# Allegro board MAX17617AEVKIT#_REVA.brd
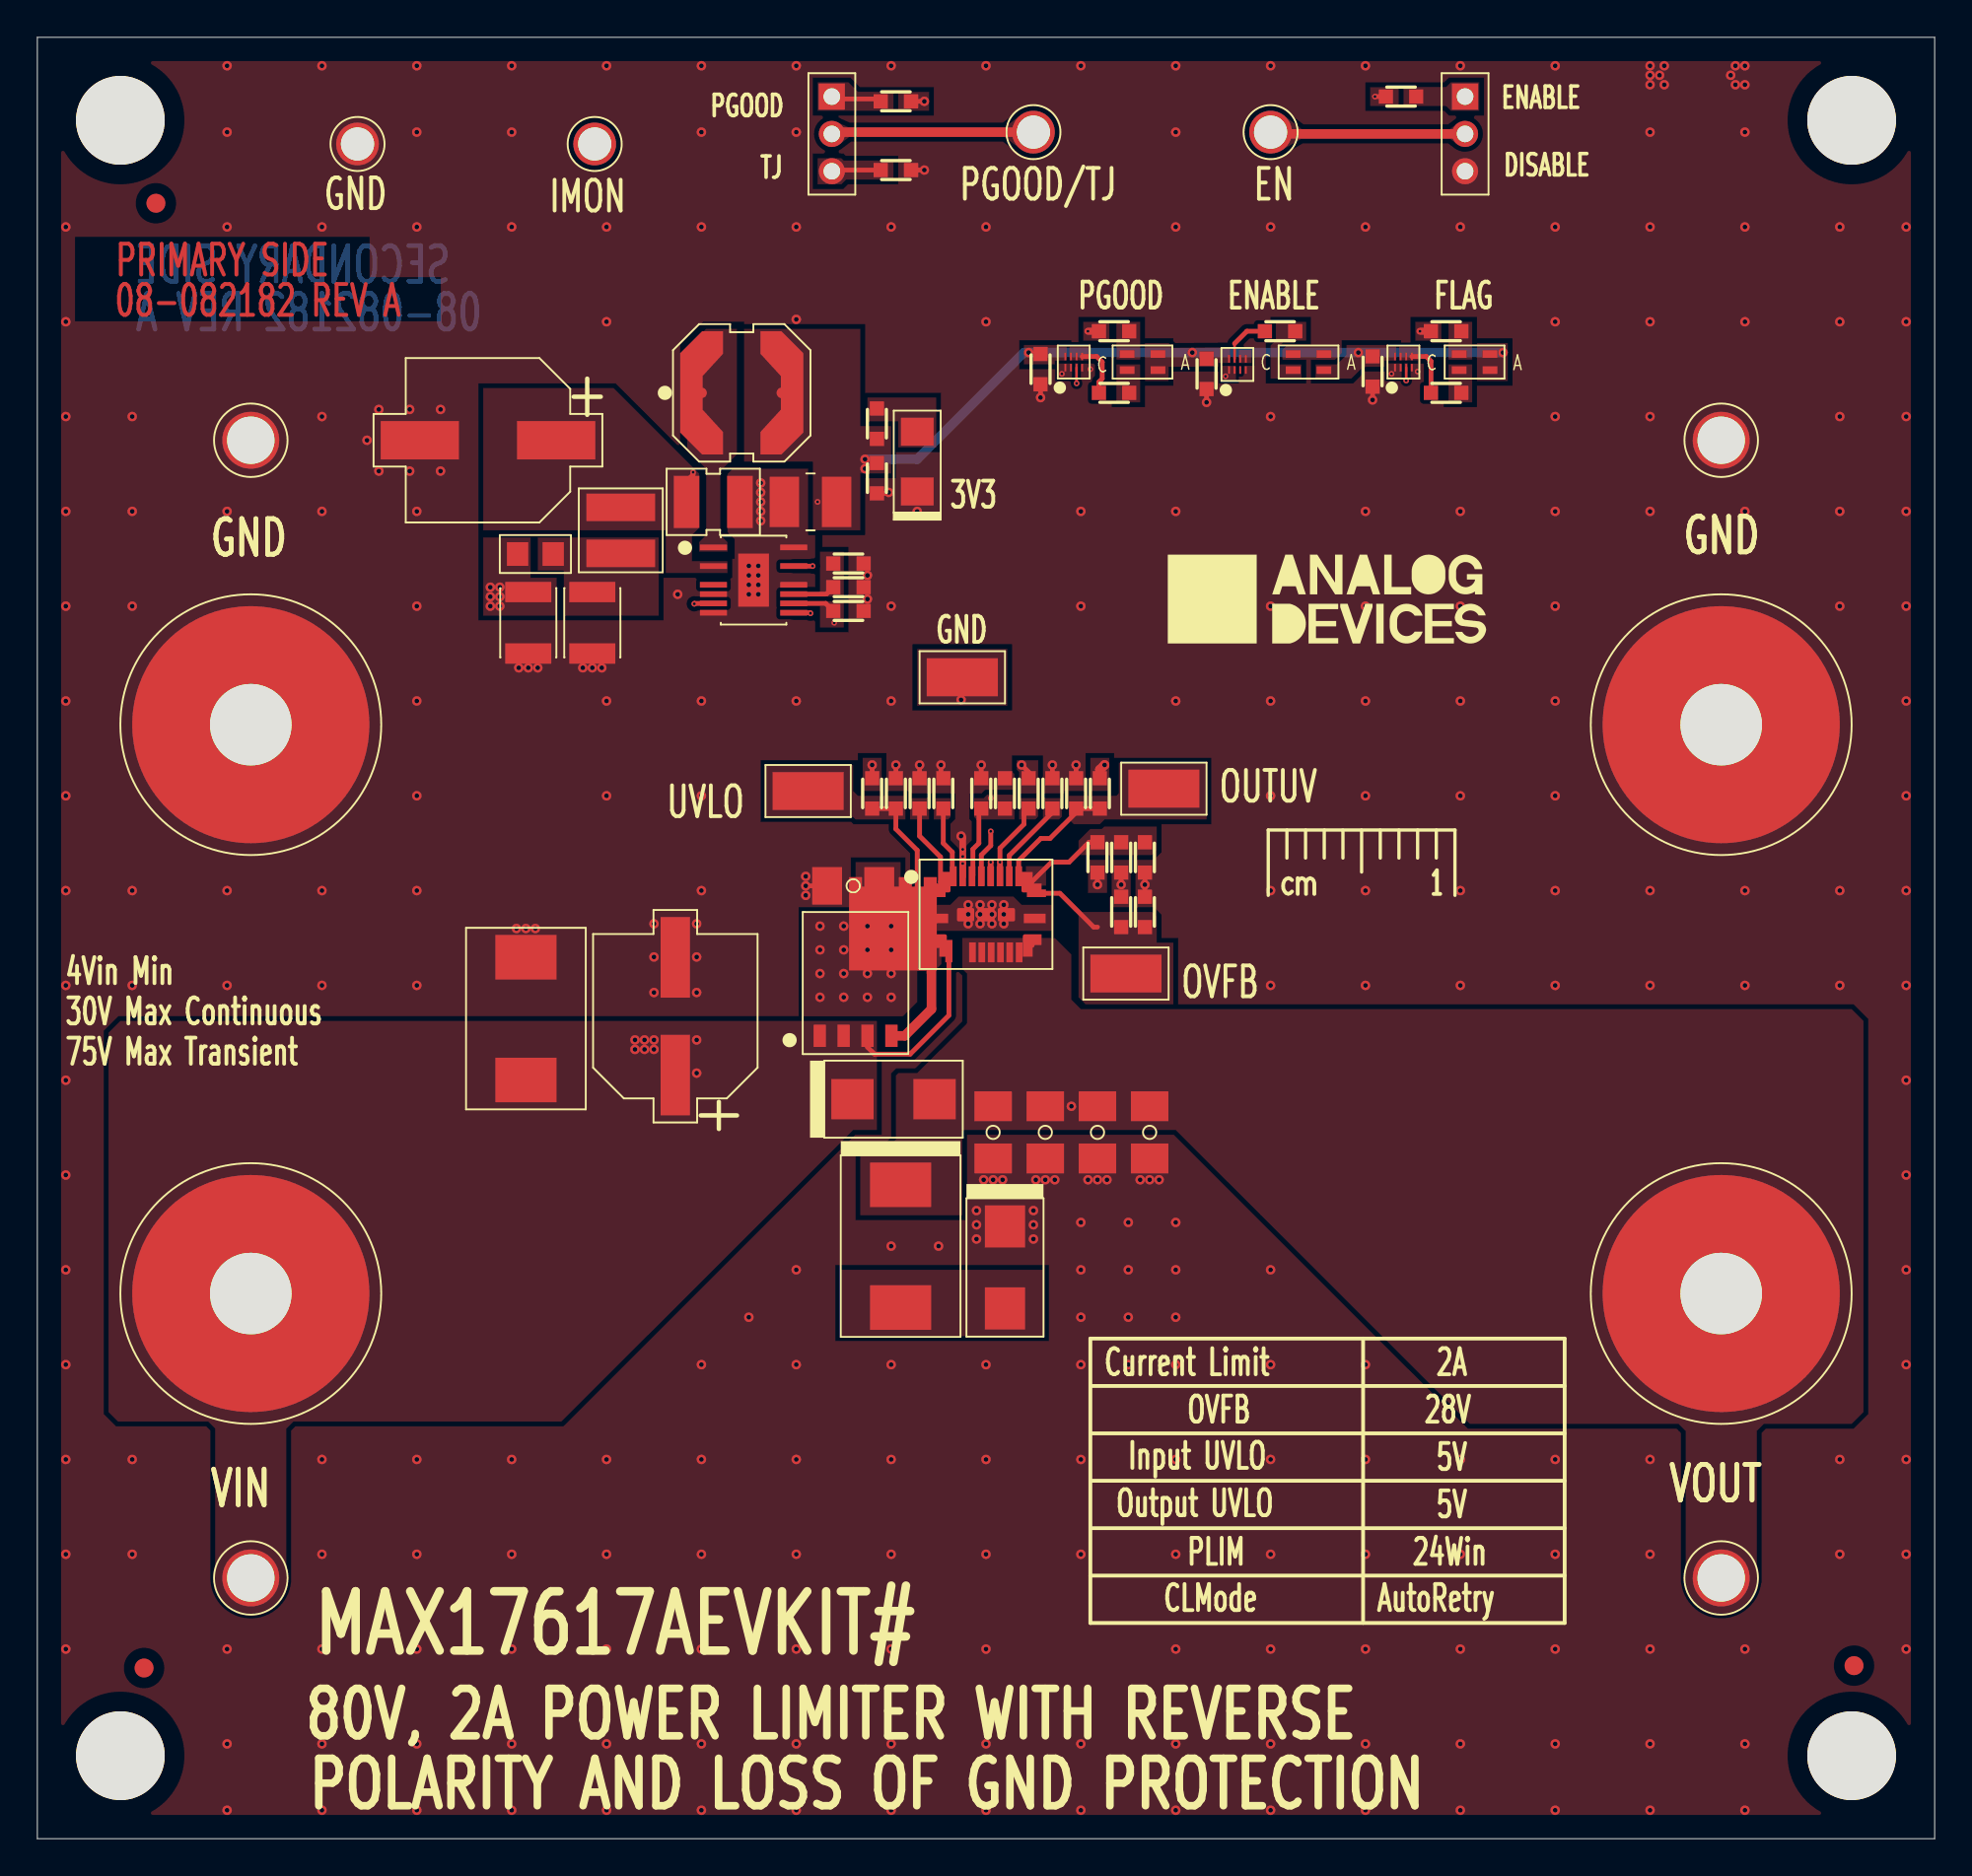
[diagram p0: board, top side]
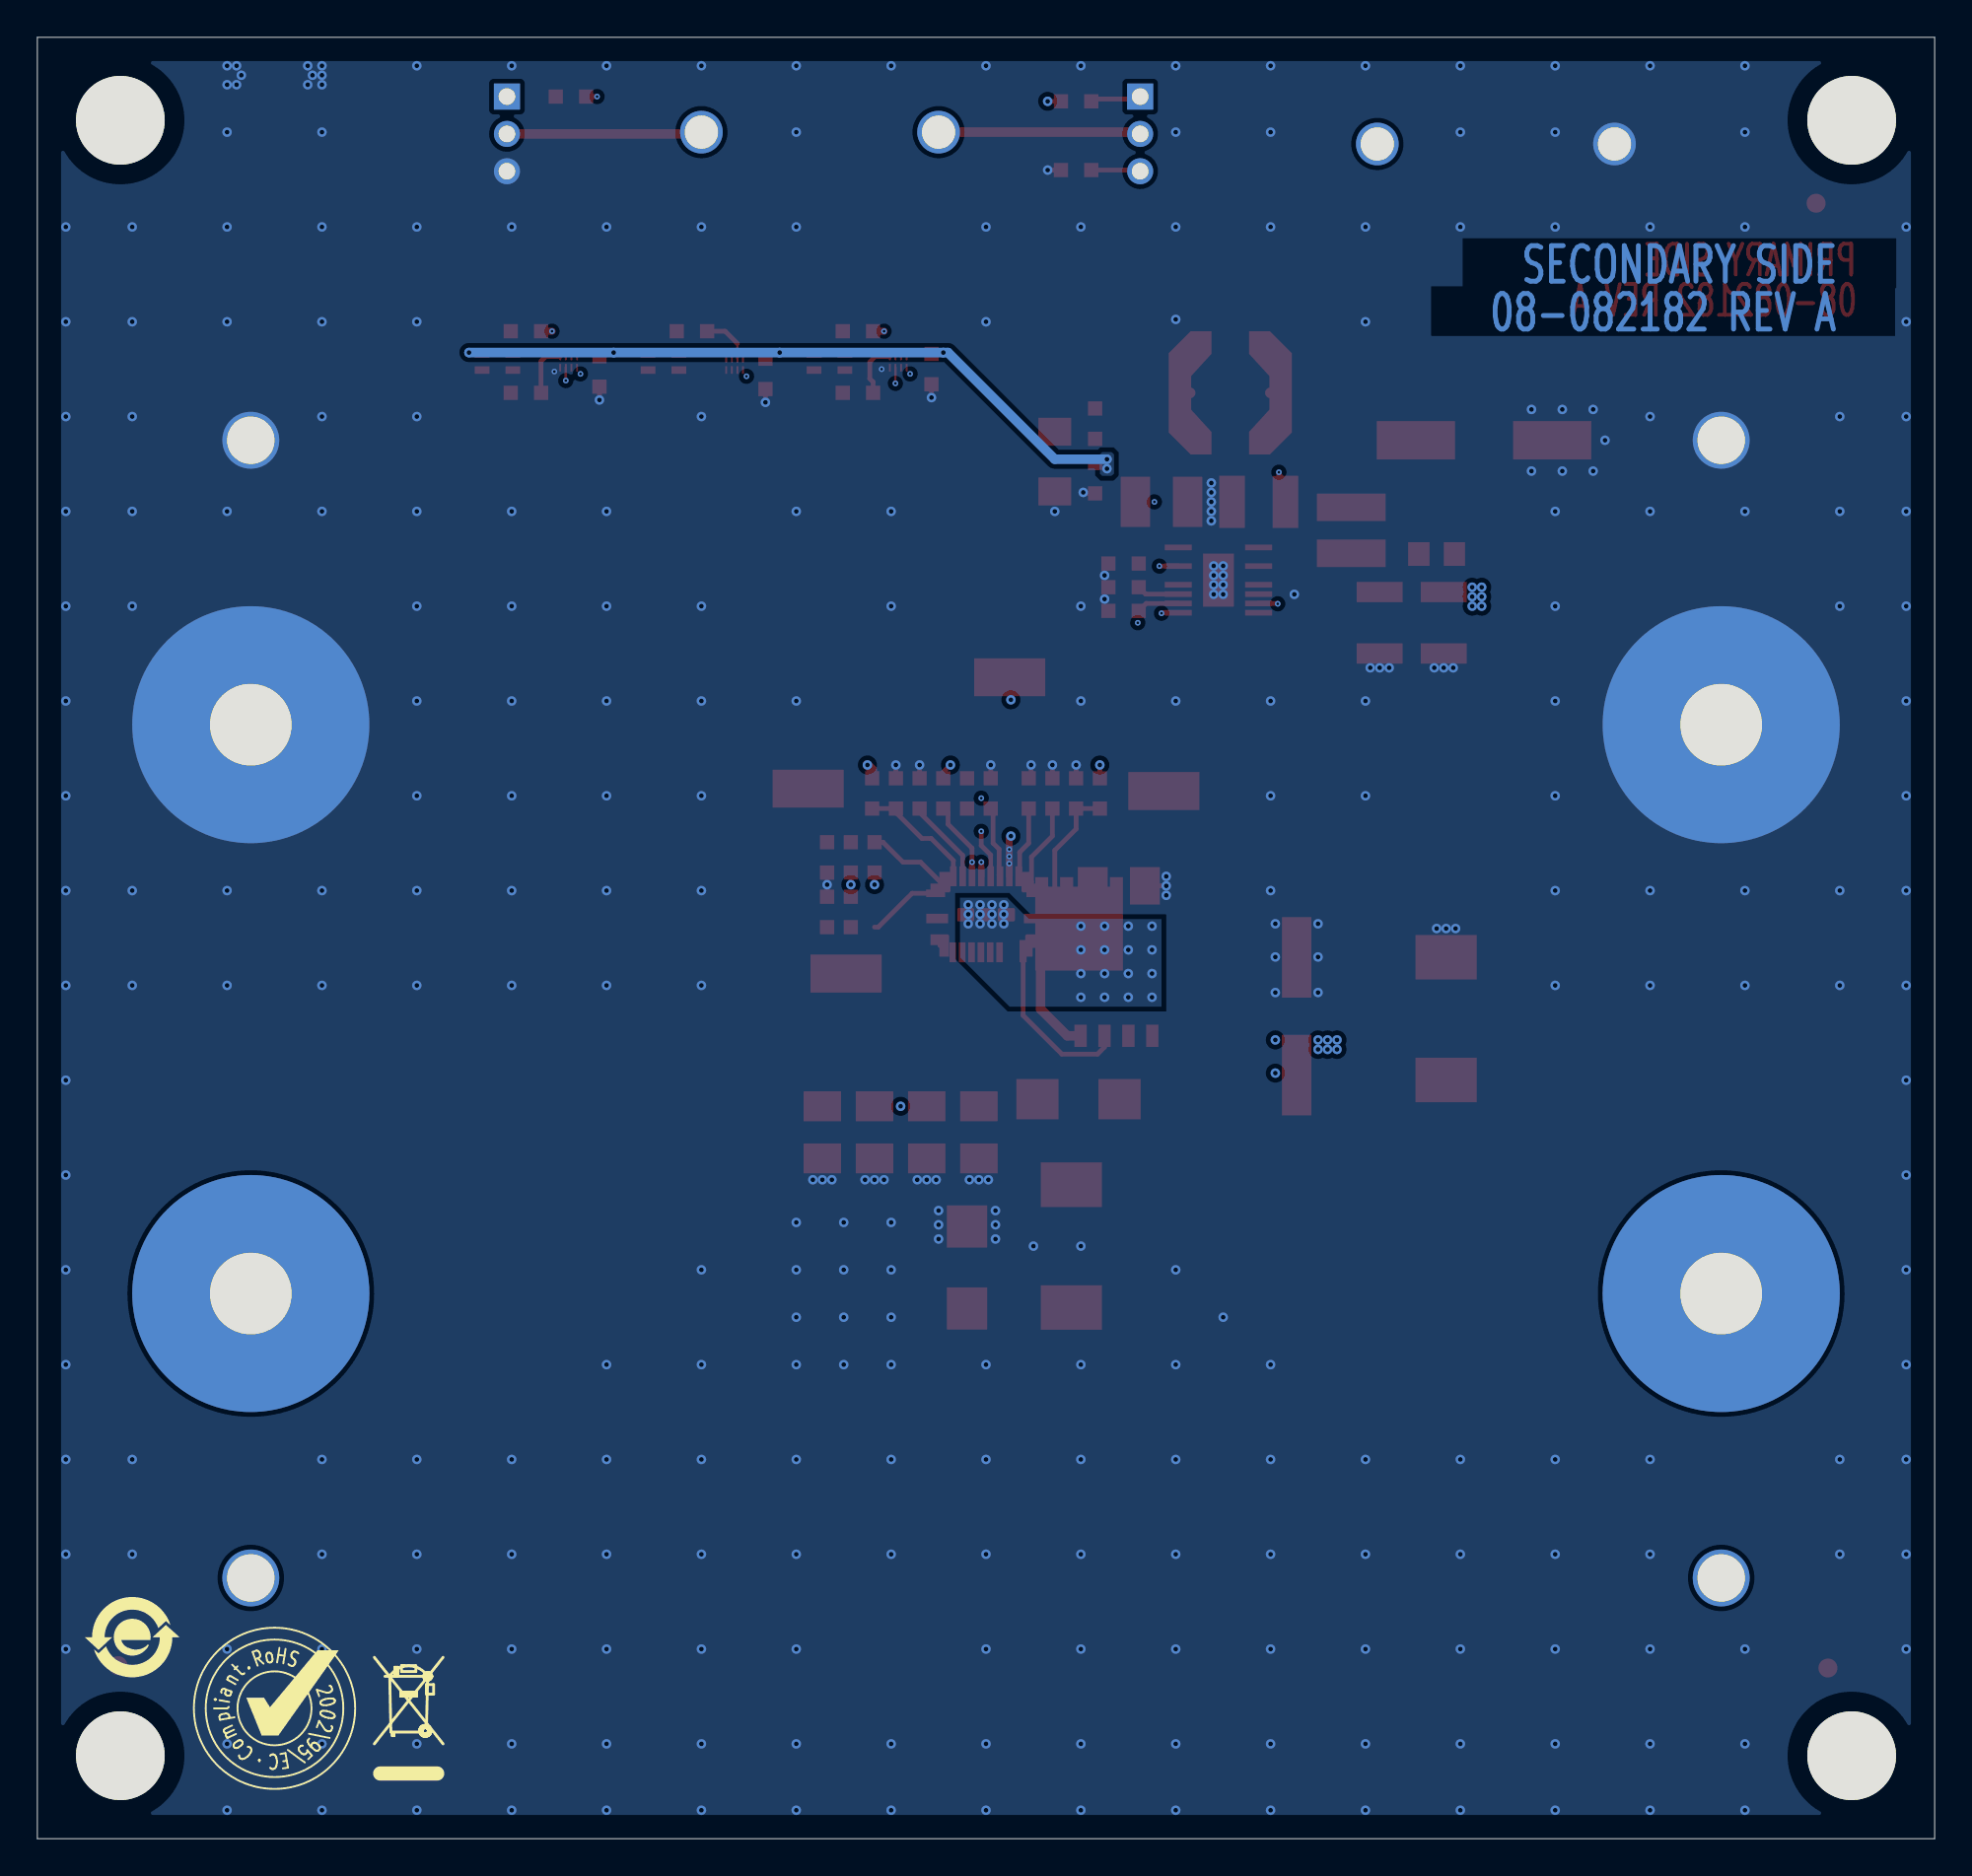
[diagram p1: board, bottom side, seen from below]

Outline 101.6 x 96.52 mm; copper layers: TOP, LAYER_2, LAYER_3, BOTTOM. Coordinates in mm from the lower left corner of the outline.
Outline path: 0,96.52 0,0 101.6,0 101.6,96.52 0,96.52

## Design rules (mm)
constraint set DEFAULT: min track width 0.254

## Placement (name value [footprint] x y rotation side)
C1  2.2uF  [C1210H87]  26.29 65.15 270 top
C2  2.2uF  [C1210H87]  29.72 65.15 270 top
C3  6.8UF  [CPLSMSQ327H413]  24.13 74.93 180 top
C5  10NF  [C0603]  43.43 65.79 0 top
C6  1UF  [C1210H110]  36.2 71.63 0 top
C7  220pF  [C0603]  43.43 67.06 0 top
C8  22uF  [C1210-2]  41.4 71.63 180 top
C11  0.1uF  [C0603]  44.96 72.9 270 top
C12  4.7UF  [CPLSMSQ327H256]  34.16 44.07 90 top
C13  0.1uF  [C0603]  71.5 78.61 270 top
C14  1uF  [C1206H71]  43.69 51.05 180 top
C15  2.2uF  [C0603]  48.51 56.01 90 top
C16  0.1uF  [C0603]  53.72 78.74 270 top
C17  4.7uF  [C1206H71]  51.18 37.85 270 top
C18  4.7uF  [C1206H71]  53.98 37.85 270 top
C19  4.7uF  [C1206H71]  56.77 37.85 270 top
C20  4.7uF  [C1206H71]  59.56 37.85 270 top
C21  0.1uF  [C0603]  62.61 78.49 270 top
C22  TBD0603  [C0603]  50.55 56.01 90 top
D1  APTB1612ESGC-F01  [LEDSML63W49H33]  76.96 79.12 180 top
D2  APTB1612ESGC-F01  [LEDSML63W49H33]  59.18 79.12 180 top
D3  APTB1612ESGC-F01  [LEDSML63W49H33]  68.07 79.12 180 top
D4  SMCJ48CA  [DO214AB_A]  26.16 43.94 90 top
D5  1KSMB62A  [DO214AA_A]  45.85 39.62 0 top
D6  SMCJ48A  [DO214AB-4]  46.23 31.75 270 top
D7  SMBJ51A  [DO214AA_A]  51.82 30.61 270 top
DS1  SML-LX1206GW-TR  [LEDSML126W63H43]  47.12 73.79 90 top
E1  330OHM  [L0805H50]  26.67 68.83 0 top
JP1  62000311121  [CNTHMHDR1X3L236W79H244]  76.45 93.34 270 top
JP2  62000311121  [CNTHMHDR1X3L236W79H244]  42.55 93.34 270 top
L1  2.2UH  [LSMSQ157H83]  31.24 70.1 90 top
L2  150UH  [LSMSQ236H138]  37.72 77.47 0 top
NOREF  -  []  -76.2 -81.28 0 top
NOREF#2  -  [unnamed#2]  97.28 9.27 0 top
NOREF#3  -  []  0 96.52 270 top
NOREF#4  -  []  289.56 206.95 0 top
NOREF#5  -  []  249.05 247.01 0 top
NOREF#6  -  []  0 96.52 0 top
NOREF#7  -  [unnamed#2]  5.71 9.14 0 top
NOREF#8  -  []  -76.2 -81.28 0 top
NOREF#9  -  []  65.91 50.55 0 top
NOREF#10  -  []  -76.2 -81.28 0 top
NOREF#11  -  []  -222.25 -151.13 0 top
NOREF#12  -  [unnamed#2]  97.16 4.45 180 top
NOREF#13  -  [unnamed#2]  4.45 4.45 180 top
NOREF#14  -  [unnamed#2]  4.45 92.08 180 top
NOREF#15  -  []  101.6 0 90 top
NOREF#16  -  []  310.64 65.34 0 top
NOREF#17  -  []  101.6 96.52 180 top
NOREF#18  -  []  53.59 102.49 0 top
NOREF#19  -  []  13.84 84.2 270 top
NOREF#20  -  []  101.6 0 90 top
NOREF#21  -  []  12.18 2.18 0 top
NOREF#22  -  []  244.98 275.02 0 top
NOREF#23  -  []  0 0 0 top
NOREF#24  -  [unnamed#2]  97.16 92.08 180 top
NOREF#25  -  []  7.24 56.26 0 top
NOREF#26  -  []  69.09 66.42 0 top
NOREF#27  -  [unnamed#2]  6.35 87.63 0 top
NOREF#28  -  []  338.84 108.52 0 top
NOREF#29  -  []  -222.25 -151.13 0 top
NOREF#30  -  []  9.78 298.32 0 top
NOREF#31  -  []  10.95 33.4 0 top
NOREF#32  -  []  81.92 3.17 180 bottom
NOREF#33  -  []  88.9 6.99 180 bottom
NOREF#34  -  []  96.52 10.79 180 bottom
Q1  SIR876ADP-T1-GE3  [SON8]  43.81 45.85 0 top
R1  7.32K  [R0603]  47.24 56.01 90 top
R2  3.83K  [R0603]  51.82 56.01 90 top
R3  220K  [R0603]  43.43 68.33 0 top
R9  1K  [R0603]  44.96 75.82 90 top
R10  1K  [R0603]  75.44 77.47 0 top
R11  1K  [R0603]  75.44 80.77 0 top
R12  442K  [R0603]  44.7 56.01 270 top
R13  100K  [R0603]  45.97 56.01 90 top
R14  64.9K  [R0603]  54.36 56.01 90 top
R15  100K  [R0603]  53.09 56.01 90 top
R16  1K  [R0603]  57.66 77.47 0 top
R17  1K  [R0603]  57.66 80.77 0 top
R18  100K  [R0603]  45.97 93.09 180 top
R19  100K  [R0603]  55.63 56.01 90 top
R20  442K  [R0603]  56.9 56.01 270 top
R22  28K  [R0603]  59.31 49.66 90 top
R23  392K  [R0603]  56.77 52.58 90 top
R24  10K  [R0603]  59.31 52.58 270 top
R25  1K  [R0603]  66.55 80.77 0 top
R26  953K  [R0603]  58.04 49.66 270 top
R27  392K  [R0603]  58.04 52.58 90 top
R28  10K  [R0603]  45.97 89.41 0 top
R29  10K  [R0603]  73.03 93.34 180 top
TP1  2501-2-00-80-00-00-07-0  [CNMILLMAX2501]  11.43 13.97 0 top
TP2  RED  [CN-BNDG-POST]  11.43 29.21 0 top
TP3  BLK  [CN-BNDG-POST]  11.43 59.69 0 top
TP4  2501-2-00-80-00-00-07-0  [CNMILLMAX2501]  11.43 74.93 0 top
TP5  2308-2-00-80-00-00-07-0  [CNMILLMAX2308]  66.04 91.44 0 top
TP6  5019  [CNKEY5019]  41.27 56.13 0 top
TP7  5019  [CNKEY5019]  49.53 62.23 0 top
TP8  5019  [CNKEY5019]  58.29 46.35 0 top
TP9  2308-2-00-80-00-00-07-0  [CNMILLMAX2308]  53.34 91.44 0 top
TP10  5019  [CNKEY5019]  60.33 56.26 0 top
TP11  2501-2-00-80-00-00-07-0  [CNMILLMAX2501]  90.17 13.97 0 top
TP12  2501-2-00-80-00-00-07-0  [CNMILLMAX2501]  90.17 74.93 0 top
TP13  RED  [CN-BNDG-POST]  90.17 29.21 0 top
TP14  BLK  [CN-BNDG-POST]  90.17 59.69 0 top
TP15  2308-2-00-80-00-00-07-0  [CNMILLMAX2308]  29.84 90.81 0 top
TP16  2308-2-00-80-00-00-07-0  [CNMILLMAX2308]  17.14 90.81 0 top
U1  MAX17617AAFD+  [QFN23_5_75X4_5_3EP]  50.8 49.53 0 top
U2  LTC3639EMSE#PBF  [MSOP16_PAD2_845X1_651_12P_05-08-1871]  38.35 67.44 270 top
U3  74LVC2G02RA3-7  [PDFN8_1_2X1]  73.15 79.12 0 top
U4  74LVC2G02RA3-7  [PDFN8_1_2X1]  55.5 79.12 0 top
U5  74LVC2G02RA3-7  [PDFN8_1_2X1]  64.26 78.99 0 top

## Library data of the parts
C1 C2 = CAP: Tolerance: 10; User Part Number: UPN; alternate symbols: (C1210H87); part number: CAP_SM-2.2UF,100V,10,E015185,C1210H87; tolerance: 10
C3 = CAPP: User Part Number: UPN; Tolerance: 20; alternate symbols: (CPLSMSQ327H413); part number: CAPP_SM-6.8UF,160V,20,E063202,CPLSMSQ327H413; tolerance: 20
C5 = CAP: Tolerance: 10; User Part Number: UPN; alternate symbols: (C0603); part number: CAP_SM-10NF,16V,10,E042810,C0603; tolerance: 10
C6 = CAP: Tolerance: 10; User Part Number: UPN; alternate symbols: (C1210H110); part number: CAP_SM-1UF,100V,10,E042933,C1210H110; tolerance: 10
C7 = CAP: Tolerance: 5; User Part Number: UPN; alternate symbols: (C0603); part number: CAP_SM-220PF,50V,5,E000417,C0603; tolerance: 5
C8 = CAP: Tolerance: 10; User Part Number: UPN; alternate symbols: (C1210-2); part number: CAP_SM-22UF,16V,10,E011548,C1210-2; tolerance: 10
C11 C13 C16 C21 = CAP: Tolerance: 10; User Part Number: UPN; alternate symbols: (C0603); part number: CAP_SM-0.1UF,16V,10,E015036,C0603; tolerance: 10
C12 = CAPP: User Part Number: UPN; Tolerance: 20; alternate symbols: (CPLSMSQ327H256); part number: CAPP_SM-4.7UF,100V,20,E046198,CPLSMSQ327H256; tolerance: 20
C14 = CAP: Tolerance: 10; User Part Number: UPN; alternate symbols: (C1206H71); part number: CAP_SM-1UF,100V,10,E031665,C1206H71; tolerance: 10
C15 = CAP: Tolerance: 10; User Part Number: UPN; alternate symbols: (C0603); part number: CAP_SM-2.2UF,10V,10,E015288,C0603; tolerance: 10
C17-C20 = CAP: Tolerance: 10; User Part Number: UPN; alternate symbols: (C1206H71); part number: CAP_SM-4.7UF,100V,10,E034771,C1206H71; tolerance: 10
C22 = CAP: User Part Number: UPN; alternate symbols: (C0603); part number: CAP_SM-TBD0603,TBD0603,TBD0603,E000382,C0603
D1-D3 = DIOLED_4P_V5: Tolerance: www.kingbright.com; User Part Number: UPN; alternate symbols: (LEDSML63W49H33); part number: DIOLED_4P_V5_SM-APTB1612ESGC-F01,2V/2.2V,N/A,E028120,LEDSML63W49H33; tolerance: www.kingbright.com
D4 = DIOTVS_BIDIR: User Part Number: UPN; Tolerance: N/A; alternate symbols: (DO214AB_A); part number: DIOTVS_BIDIR_SM-SMCJ48CA,48V,N/A,E059886,DO214AB_A; tolerance: N/A
D5 = DIOTVS: User Part Number: UPN; Tolerance: N/A; alternate symbols: (DO214AA_A); part number: DIOTVS_SM-1KSMB62A,53V,N/A,E059891,DO214AA_A; tolerance: N/A
D6 = DIOTVS: User Part Number: UPN; Tolerance: N/A; alternate symbols: (DO214AB-4); part number: DIOTVS_SM-SMCJ48A,N/A,N/A,E019000,DO214AB-4; tolerance: N/A
D7 = DIOZNR: User Part Number: UPN; Tolerance: N/A; alternate symbols: (DO214AA_A); part number: DIOZNR_SM-SMBJ51A,51V,N/A,E043431,DO214AA_A; tolerance: N/A
DS1 = DIOLED: Tolerance: N/A; User Part Number: UPN; alternate symbols: (LEDSML126W63H43); part number: DIOLED_SM-SML-LX1206GW-TR,N/A,N/A,E008009,LEDSML126W63H43; tolerance: N/A
E1 = FERRITE: Tolerance: 25; User Part Number: UPN; alternate symbols: (L0805H50); part number: FERRITE_SM-330OHM,25,E016893,L0805H50; tolerance: 25
JP1 JP2 = CN3P: User Part Number: UPN; Tolerance: N/A; alternate symbols: (CNTHMHDR1X3L236W79H244); part number: CN3P_TH-62000311121,E033291,CNTHMHDR1X3L236W79H244; tolerance: N/A
L1 = IND: User Part Number: UPN; Tolerance: 20; alternate symbols: (LSMSQ157H83); part number: IND_SM-2.2UH,20,E051506,LSMSQ157H83; tolerance: 20
L2 = IND: User Part Number: UPN; Tolerance: 20; alternate symbols: (LSMSQ236H138); part number: IND_SM-150UH,20,E046122,LSMSQ236H138; tolerance: 20
Q1 = TRANNMOSFET8P: Tolerance: N/A; User Part Number: UPN; alternate symbols: (SON8); part number: TRANNMOSFET8P_SM-SIR876ADP-T1-GE3,E059889,SON8; tolerance: N/A
R1 = RES: Tolerance: 1; User Part Number: UPN; alternate symbols: (R0603); part number: RES_SM-7.32K,E024630,1/10W,1,R0603; tolerance: 1
R2 = RES: Tolerance: 1; User Part Number: UPN; alternate symbols: (R0603); part number: RES_SM-3.83K,E066481,1/10W,1,R0603; tolerance: 1
R3 = RES: Tolerance: 1; User Part Number: UPN; alternate symbols: (R0603); part number: RES_SM-220K,E042876,1/10W,1,R0603; tolerance: 1
R9-R11 R16 R17 R25 = RES: Tolerance: 1; User Part Number: UPN; alternate symbols: (R0603); part number: RES_SM-1K,E003678,1/10W,1,R0603; tolerance: 1
R12 R20 = RES: Tolerance: 1; User Part Number: UPN; alternate symbols: (R0603); part number: RES_SM-442K,E042881,1/10W,1,R0603; tolerance: 1
R13 R15 R18 R19 = RES: Tolerance: 1; User Part Number: UPN; alternate symbols: (R0603); part number: RES_SM-100K,E010279,1/10W,1,R0603; tolerance: 1
R14 = RES: Tolerance: 1; User Part Number: UPN; alternate symbols: (R0603); part number: RES_SM-64.9K,E010256,1/10W,1,R0603; tolerance: 1
R22 = RES: Tolerance: 1; User Part Number: UPN; alternate symbols: (R0603); part number: RES_SM-28K,E019092,1/10W,1,R0603; tolerance: 1
R23 R27 = RES: Tolerance: 1; User Part Number: UPN; alternate symbols: (R0603); part number: RES_SM-392K,E060084,1/10W,1,R0603; tolerance: 1
R24 R28 R29 = RES: Tolerance: 1; User Part Number: UPN; alternate symbols: (R0603); part number: RES_SM-10K,E003671,1/10W,1,R0603; tolerance: 1
R26 = RES: Tolerance: 1; User Part Number: UPN; alternate symbols: (R0603); part number: RES_SM-953K,E067819,1/10W,1,R0603; tolerance: 1
TP1 TP4 TP11 TP12 = CNTP1P: User Part Number: UPN; Tolerance: N/A; alternate symbols: (CNMILLMAX2501); part number: CNTP1P_TH-2501-2-00-80-00-00-07-0,E031108,CNMILLMAX2501; tolerance: N/A
TP2 TP13 = CNTP1P: Tolerance: N/A; User Part Number: UPN; alternate symbols: (CN-BNDG-POST); part number: CNTP1P_TH-RED,E005767,CN-BNDG-POST; tolerance: N/A
TP3 TP14 = CNTP1P: Tolerance: N/A; User Part Number: UPN; alternate symbols: (CN-BNDG-POST); part number: CNTP1P_TH-BLK,E005768,CN-BNDG-POST; tolerance: N/A
TP5 TP9 TP15 TP16 = CNTP1P: User Part Number: UPN; Tolerance: N/A; alternate symbols: (CNMILLMAX2308); part number: CNTP1P_TH-2308-2-00-80-00-00-07-0,E030692,CNMILLMAX2308; tolerance: N/A
TP6-TP8 TP10 = CNTP1P: User Part Number: UPN; Tolerance: N/A; alternate symbols: (CNKEY5019); part number: CNTP1P_SM-5019,E021431,CNKEY5019; tolerance: N/A
U1 = ADMAX17617A: User Part Number: UPN; Tolerance: N/A; alternate symbols: (QFN23_5_75X4_5_3EP); part number: ADMAX17617A_SM-MAX17617AAFD+,E059964,QFN23_5_75X4_5_3EP; tolerance: N/A
U2 = ADLTC3639: Tolerance: N/A; User Part Number: UPN; alternate symbols: (MSOP16_PAD2_845X1_651_12P_05-08-1871); part number: ADLTC3639_SM-LTC3639EMSE#PBF,E048616,MSOP16_PAD2_845X1_651_12P_05-08-1871; tolerance: N/A
U3-U5 = 7402_V2: User Part Number: UPN; Tolerance: N/A; alternate symbols: (PDFN8_1_2X1); part number: 7402_V2_SM-74LVC2G02RA3-7,E026705,PDFN8_1_2X1; tolerance: N/A

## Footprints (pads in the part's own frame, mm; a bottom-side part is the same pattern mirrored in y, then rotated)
C0603
  rect 0.762x0.762 smd: 1(-0.813,0) 2(0.813,0)
C1206H71
  rect 1.6x2.007 smd: 1(-1.397,0) 2(1.397,0)
C1210-2
  rect 1.575x2.692 smd: 1(-1.397,0) 2(1.397,0)
C1210H87
  rect 1.092x2.464 smd: 1(-1.646,0) 2(1.646,0)
C1210H110
  rect 1.372x2.794 smd: 1(-1.431,0) 2(1.431,0)
CN-BNDG-POST
  round 12.7 hole 4.369: 1(0,0)
CNKEY5019
  rect 3.81x2.032 smd: 1(0,0)
CNMILLMAX2308
  round 2.286 hole 1.778: 1(0,0)
CNMILLMAX2501
  round 3.048 hole 2.54: 1(0,0)
CNTHMHDR1X3L236W79H244
  rect 1.397x1.397 hole 0.889: 1(0,0)
  round 1.397 hole 0.889: 2(2,0) 3(4,0)
CPLSMSQ327H256
  rect 4.318x1.575 smd: N(3.154,0) P(-3.154,0)
CPLSMSQ327H413
  rect 4.191x2.057 smd: N(3.65,0) P(-3.65,0)
DO214AA_A
  rect 2.261x2.159 smd: A(2.197,0) C(-2.197,0)
DO214AB-4
  rect 2.388x3.277 smd: A(3.289,0) C(-3.289,0)
DO214AB_A
  rect 2.388x3.277 smd: 1(-3.289,0) 2(3.289,0)
L0805H50
  rect 1.143x1.27 smd: 1(-0.953,0) 2(0.953,0)
LEDSML63W49H33
  rect 0.787x0.406 smd: 1(-0.825,-0.43) 2(0.825,-0.43) 3(-0.825,0.43) 4(0.825,0.43)
LEDSML126W63H43
  rect 1.499x1.753 smd: A(1.6,0) C(-1.6,0)
LSMSQ157H83
  rect 1.473x3.683 smd: 1(-1.232,0) 2(1.232,0)
LSMSQ236H138
  custom 0.575x0.575 smd: 1(-2.151,0) 2(2.151,0)
MSOP16_PAD2_845X1_651_12P_05-08-1871
  rect 0.305x1.448 smd: 1(-1.75,-2.15) 3(-0.75,-2.15) 5(0.25,-2.15) 6(0.75,-2.15) 7(1.25,-2.15) 8(1.75,-2.15) 9(1.75,2.15) 10(1.25,2.15) 11(0.75,2.15) 12(0.25,2.15) 14(-0.75,2.15) 16(-1.75,2.15)
  rect 2.845x1.651 smd: 17(0,0)
PDFN8_1_2X1
  rect 0.102x0.406 smd: 1(-0.45,-0.3) 2(-0.15,-0.3) 3(0.15,-0.3) 4(0.45,-0.3) 5(0.45,0.3) 6(0.15,0.3) 7(-0.15,0.3) 8(-0.45,0.3)
QFN23_5_75X4_5_3EP
  custom 0.268x0.268 smd: 1(-2.436,1.723) 15(2.436,1.723)
  rect 1.016x0.406 smd: 2(-2.676,1.125) 14(2.7,1.125)
  rect 1.168x0.508 smd: 3(-2.612,-0.225) 13(2.612,-0.225)
  custom 0.218x0.218 smd: 4(-2.536,-1.674)
  rect 0.381x1.194 smd: 5(-1.988,-1.975)
  rect 0.356x1.067 smd: 6(-0.725,-2.038) 7(-0.225,-2.038) 8(0.275,-2.038) 9(0.775,-2.038) 10(1.275,-2.038) 11(1.775,-2.038) 16(1.75,2.038) 17(1.25,2.038) 18(0.75,2.038) 19(0.25,2.038) 20(-0.25,2.038) 21(-0.75,2.038) 22(-1.25,2.038) 23(-1.75,2.038)
  custom 0.249x0.249 smd: 12(2.473,-1.674)
  custom 0.179x0.179 smd: 24(-1.092,-0.023) 25(0,-0.023) 26(1.092,-0.023)
R0603
  rect 0.762x0.762 smd: 1(-0.813,0) 2(0.813,0)
SON8
  rect 0.66x1.194 smd: 1(-1.92,-2.828) 2(-0.64,-2.828) 3(0.64,-2.828) 4(1.92,-2.828)
  custom 1.175x1.175 smd: 5(2,3.171)
  round 0.127 smd: 6(0.678,3.211) 7(-0.68,3.236) 8(-2.002,3.223)
unnamed#2
  round 1.016 smd: (0,0)

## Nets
3V3: C8.1 C11.1 C13.1 C16.1 C21.1 D1.1 D1.3 D2.1 D2.3 D3.3 L2.2(N2) R9.1 R15.2(N2) R18.1 R29.2(N2) U2.9 U3.8(VCC) U4.8(VCC) U5.8(VCC)
VIN: C1.1 C12.P D4.1 D5.C E1.1 Q1.1 Q1.2 Q1.3(S3) R12.1 R23.1 TP1.1(N1) TP2.1(N1) U1.5
EN: JP1.2 TP5.1(N1) U1.19 U5.1 U5.2
FLAG: R15.1 U1.18 U3.1 U3.2
GROUND: C1.2(N2) C2.2(N2) C3.N(N2) C5.2(N2) C6.2(N2) C7.2(N2) C8.2(N2) C11.2(N2) C12.N(N2) C13.2(N2) C14.2(N2) C15.2(N2) C16.2(N2) C17.2(N2) C18.2(N2) C19.2(N2) C20.2(N2) C21.2(N2) C22.2(N2) D3.1 D3.2 D4.2(N2) D7.C DS1.C JP1.3(N3) R1.2(N2) R2.2(N2) R3.2(N2) R13.2(N2) R14.2(N2) R19.2(N2) R22.2(N2) R24.2(N2) R28.2(N2) TP3.1(N1) TP4.1(N1) TP7.1(N1) TP12.1(N1) TP14.1(N1) TP16.1(N1) U1.22 U2.6(VPRG2) U2.8 U2.12 U2.16 U2.17 U3.4 U4.4 U5.4
PGOOD/TJ: JP2.2 TP9.1(N1) U1.20 U4.1 U4.2
UNNAMED_1_ADLTC3639_I30_ISET: C7.1 R3.1 U2.11
UNNAMED_1_ADLTC3639_I30_RUN: C3.P C6.1 L1.2(N2) U2.3 U2.14
UNNAMED_1_ADLTC3639_I30_SS: C5.1 U2.7 U2.10
UNNAMED_1_ADLTC3639_I30_SW: L2.1 U2.1
UNNAMED_1_CAP_I4_N1: C2.1 E1.2(N2) L1.1
UNNAMED_1_DIOLED_I24_P: DS1.A(P) R9.2(N2)
UNNAMED_2_7402V2_I1_1Y: R10.1 U3.5 U3.6 U3.7
UNNAMED_2_7402V2_I1_2Y: R11.1 U3.3
UNNAMED_2_7402V2_I29_1Y: R16.1 U4.5 U4.6 U4.7
UNNAMED_2_7402V2_I29_2Y: R17.1 U4.3
UNNAMED_2_7402V2_I64_1Y: R25.1 U5.7
UNNAMED_2_7402V2_I64_2A: U5.5 U5.6
UNNAMED_2_ADMAX17617A_I102_GN: Q1.4 U1.4
UNNAMED_2_ADMAX17617A_I102_IMON: C22.1 R2.1 TP15.1(N1) U1.21
UNNAMED_2_ADMAX17617A_I102_IN1: C14.1 Q1.5 Q1.6 Q1.7 Q1.8 U1.3 U1.13 U1.24 U1.25 U1.26
UNNAMED_2_ADMAX17617A_I102_ISTART: R14.1 U1.17
UNNAMED_2_ADMAX17617A_I102_OUTUV: R19.1 R20.2(N2) TP10.1(N1) U1.16
UNNAMED_2_ADMAX17617A_I102_OVFB: R22.1 R26.2(N2) TP8.1(N1) U1.14
UNNAMED_2_ADMAX17617A_I102_PLIM: R23.2(N2) R24.1 R27.2(N2) U1.15
UNNAMED_2_ADMAX17617A_I102_SETI: R1.1 U1.1
UNNAMED_2_ADMAX17617A_I102_UVLO: R12.2(N2) R13.1 TP6.1(N1) U1.2
UNNAMED_2_ADMAX17617A_I102_VCC: C15.1 U1.23(VCC)
UNNAMED_2_CN3P_I11_N1: JP1.1 R29.1
UNNAMED_2_CN3P_I68_N1: JP2.1 R18.2(N2)
UNNAMED_2_CN3P_I68_N3: JP2.3(N3) R28.1
UNNAMED_2_DIOLED4PV5_I19_C1: D1.2 R11.2(N2)
UNNAMED_2_DIOLED4PV5_I19_C2: D1.4(C2) R10.2(N2)
UNNAMED_2_DIOLED4PV5_I31_C1: D2.2 R17.2(N2)
UNNAMED_2_DIOLED4PV5_I31_C2: D2.4(C2) R16.2(N2)
UNNAMED_2_DIOLED4PV5_I74_C2: D3.4(C2) R25.2(N2)
UNNAMED_2_DIOTVS_I103_P: D6.A(P) D7.A(P)
VOUT: C17.1 C18.1 C19.1 C20.1 D5.A(P) D6.C R20.1 R26.1 R27.1 TP11.1(N1) TP13.1(N1) U1.6 U1.7 U1.8 U1.9 U1.10 U1.11 U1.12

Pads without a net: U2 5; U5 3

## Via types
v1: diameter 0.305, hole 0.152, TOP to BOTTOM, 23 vias
v2: diameter 0.508, hole 0.254, TOP to BOTTOM, 393 vias

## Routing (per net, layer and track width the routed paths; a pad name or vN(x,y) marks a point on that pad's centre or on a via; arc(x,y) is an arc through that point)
3V3: length 101.2
  TOP w0.254: v1(41.4,65.66) 41.37,65.69 U2.9 ; v2(52.7,57.53) 53.09,57.15 R15.2 ; R18.1 v2(47.5,93.09) ; R29.2 v1(71.63,93.34)
  LAYER_3 w0.254: v2(70.74,79.63) 70.74,80.84 70.36,81.22 70.36,92.08 v1(71.63,93.34) ; v1(41.78,71.63) 41.78,70.1 42.67,69.22 42.67,67.56 41.4,66.29 v1(41.4,65.66)
  LAYER_3 w0.508: v2(47.5,93.09) 47.5,90.68 44.32,87.5 v2(44.32,73.91) ; v2(44.32,73.41) 44.32,71.88 52.45,63.75 52.45,57.78 v2(52.7,57.53)
  LAYER_3 w0.635: v2(44.32,73.41) v2(44.32,73.91)
  BOTTOM w0.508: v2(44.32,73.91) 47.12,73.91 52.83,79.63 v2(53.09,79.63) v2(61.85,79.63) v2(70.74,79.63) v2(78.49,79.63)
VIN: length 57.9
  TOP w0.254: R23.1 v2(56.77,51.12) ; R12.1 v2(44.7,57.53) ; Q1.3 44.46,42.41 44.83,42.04 46.74,42.04 48.81,44.11 U1.5
  LAYER_3 w0.254: v2(35.31,41.02) 51.56,41.02 56.01,45.47 56.01,50.42 v2(56.77,51.12) ; v2(35.31,42.8) 36.2,43.69 36.2,49.02 v2(44.7,57.53)
  vias: v2(24.26,67.06) v2(24.26,66.55) v2(24.26,66.04) v2(24.77,67.06) v2(24.77,66.55) v2(24.77,66.04) v2(32,42.8) v2(32,42.29) v2(32.51,42.8) v2(32.51,42.29) v2(33.02,42.8) v2(33.02,42.29)
EN: length 56.5
  TOP w0.254: 66.13,91.35 TP5.1
  TOP w0.305: U1.19 v1(51.05,52.32)
  TOP w0.508: JP1.2 66.13,91.35
  LAYER_3 w0.254: TP5.1 63.63,89.03 v1(63.63,78.36) 63.63,76.58 54.99,67.94 54.99,56.77 51.05,52.83 v1(51.05,52.32)
FLAG: length 40
  TOP w0.254: v1(51.55,52.32) 51.55,53.07 52.83,54.36 52.83,54.94 R15.1
  TOP w0.305: U1.18 v1(51.55,52.32)
  LAYER_3 w0.254: v1(72.52,78.49) 71.75,78.49 56.26,62.99 56.26,56.26 52.32,52.32 v1(51.55,52.32)
GROUND: length 19.8
  TOP w0.254: C21.2 v2(62.61,76.96) ; R24.2 v2(59.31,51.12) R22.2 ; R13.2 v2(45.97,57.53) ; C13.2 v2(71.5,77.09) ; v2(54.36,57.53) R14.2 ; R28.2 v2(47.5,89.41) ; v2(55.63,57.53) R19.2 ; C16.2 v2(53.72,77.22) ; R1.2 v2(47.24,57.53) ; v2(45.59,72.14) 45.54,72.09 C11.2 ; C14.2 v2(41.15,51.05) ; C15.2 48.39,56.95 v2(48.39,57.53) ; v2(50.55,57.53) C22.2
  TOP w0.356: v2(49.47,53.72) 49.56,53.63 v1(49.56,53.01) v1(49.56,52.63) v1(49.56,52.25) 49.55,52.24 U1.22
  LAYER_3 w0.635: v2(49.47,53.72) v2(49.47,61.02)
  vias: v1(56.39,78.74) v1(73.91,78.61) v2(1.52,86.36) v2(1.52,81.28) v2(1.52,76.2) v2(1.52,71.12) v2(1.52,66.04) v2(1.52,60.96) v2(1.52,55.88) v2(1.52,50.8) v2(1.52,45.72) v2(1.52,40.64) v2(1.52,35.56) v2(1.52,30.48) v2(1.52,25.4) v2(1.52,20.32) v2(1.52,15.24) v2(1.52,10.16) v2(5.08,76.2) v2(5.08,71.12) v2(5.08,66.04) v2(5.08,50.8) v2(5.08,45.72) v2(5.08,20.32) v2(5.08,15.24) v2(10.16,95) v2(10.16,91.44) v2(10.16,86.36) v2(10.16,71.12) v2(10.16,50.8) v2(10.16,45.72) v2(10.16,10.16) v2(10.16,5.08) v2(10.16,1.52) v2(15.24,95) v2(15.24,86.36) v2(15.24,76.2) v2(15.24,71.12) v2(15.24,50.8) v2(15.24,45.72) v2(15.24,20.32) v2(15.24,15.24) v2(15.24,10.16) v2(15.24,5.08) v2(15.24,1.52) v2(17.65,74.93) v2(18.29,76.58) v2(18.29,73.28) v2(19.94,76.58) v2(19.94,73.28) v2(20.32,95) v2(20.32,91.44) v2(20.32,86.36) v2(20.32,71.12) v2(20.32,66.04) v2(20.32,60.96) v2(20.32,55.88) v2(20.32,50.8) v2(20.32,45.72) v2(20.32,20.32) v2(20.32,15.24) v2(20.32,10.16) v2(20.32,5.08) v2(20.32,1.52) v2(21.59,76.58) v2(21.59,73.28) v2(25.4,95) v2(25.4,91.44) v2(25.4,86.36) v2(25.4,20.32) v2(25.4,15.24) v2(25.4,10.16) v2(25.4,5.08) v2(25.4,1.52) v2(25.65,48.77) v2(25.78,62.74) v2(26.16,48.77) v2(26.29,62.74) v2(26.67,48.77) v2(26.8,62.74) v2(29.21,62.74) v2(29.72,62.74) v2(30.23,62.74) v2(30.48,95) v2(30.48,86.36) v2(30.48,81.28) v2(30.48,60.96) v2(30.48,55.88) v2(30.48,20.32) v2(30.48,15.24) v2(30.48,10.16) v2(30.48,5.08) v2(30.48,1.52) v2(33.02,49.02) v2(33.02,47.24) v2(33.02,45.34) v2(34.29,66.67) v2(35.31,49.02) v2(35.31,47.24) v2(35.31,45.34) v2(35.56,95) v2(35.56,91.44) v2(35.56,86.36) v2(35.56,60.96) v2(35.56,55.88) v2(35.56,50.8) v2(35.56,25.4) v2(35.56,20.32) v2(35.56,15.24) v2(35.56,10.16) v2(35.56,5.08) v2(35.56,1.52) v2(38.1,68.2) v2(38.1,67.69) v2(38.1,67.18) v2(38.1,66.67) v2(38.1,27.94) v2(38.61,68.2) v2(38.61,67.69) v2(38.61,67.18) v2(38.61,66.67) v2(38.73,72.64) v2(38.73,72.14) v2(38.73,71.63) v2(38.73,71.12) v2(38.73,70.61) v2(40.64,95) v2(40.64,91.44) v2(40.64,86.36) v2(40.64,81.41) v2(40.64,60.96) v2(40.64,30.48) v2(40.64,25.4) v2(40.64,20.32) v2(40.64,15.24) v2(40.64,10.16) v2(40.64,5.08) v2(40.64,1.52) v2(41.15,51.56) v2(41.15,50.55) v2(44.45,67.69) v2(44.45,66.42) v2(45.72,95) v2(45.72,86.36) v2(45.72,66.04) v2(45.72,60.96) v2(45.72,31.75) v2(45.72,25.4) v2(45.72,20.32) v2(45.72,15.24) v2(45.72,10.16) v2(45.72,5.08) v2(45.72,1.52) v2(47.12,71.12) v2(48.26,31.75) v2(50.29,33.66) v2(50.29,32.89) v2(50.29,32.13) v2(50.67,35.31) v2(50.8,95) v2(50.8,86.36) v2(50.8,81.28) v2(50.8,25.4) v2(50.8,20.32) v2(50.8,15.24) v2(50.8,10.16) v2(50.8,5.08) v2(50.8,1.52) v2(51.18,35.31) v2(51.69,35.31) v2(53.34,33.66) v2(53.34,32.89) v2(53.34,32.13) v2(53.47,35.31) v2(53.98,35.31) v2(54.48,35.31) v2(55.88,95) v2(55.88,71.12) v2(55.88,66.04) v2(55.88,33.02) v2(55.88,30.48) v2(55.88,27.94) v2(55.88,25.4) v2(55.88,20.32) v2(55.88,15.24) v2(55.88,5.08) v2(55.88,1.52) v2(56.26,35.31) v2(56.77,35.31) v2(57.28,35.31) v2(58.42,33.02) v2(58.42,30.48) v2(58.42,27.94) v2(58.42,25.4) v2(59.05,35.31) v2(59.56,35.31) v2(60.07,35.31) v2(60.96,95) v2(60.96,91.44) v2(60.96,86.36) v2(60.96,71.12) v2(60.96,60.96) v2(60.96,33.02) v2(60.96,30.48) v2(60.96,27.94) v2(60.96,25.4) v2(60.96,20.32) v2(60.96,15.24) v2(60.96,10.16) v2(60.96,5.08) v2(60.96,1.52) v2(66.04,95) v2(66.04,86.36) v2(66.04,76.2) v2(66.04,66.04) v2(66.04,60.96) v2(66.04,55.88) v2(66.04,50.8) v2(66.04,45.72) v2(66.04,30.48) v2(66.04,25.4) v2(66.04,20.32) v2(66.04,15.24) v2(66.04,10.16) v2(66.04,5.08) v2(66.04,1.52) v2(71.12,95) v2(71.12,86.36) v2(71.12,71.12) v2(71.12,66.04) v2(71.12,60.96) v2(71.12,55.88) v2(71.12,50.8) v2(71.12,45.72) v2(71.12,25.4) v2(71.12,20.32) v2(71.12,15.24) v2(71.12,10.16) v2(71.12,5.08) v2(71.12,1.52) v2(76.2,95) v2(76.2,86.36) v2(76.2,71.12) v2(76.2,66.04) v2(76.2,60.96) v2(76.2,55.88) v2(76.2,50.8) v2(76.2,45.72) v2(76.2,20.32) v2(76.2,15.24) v2(76.2,10.16) v2(76.2,5.08) v2(76.2,1.52) v2(81.28,95) v2(81.28,86.36) v2(81.28,81.28) v2(81.28,76.2) v2(81.28,71.12) v2(81.28,66.04) v2(81.28,60.96) v2(81.28,55.88) v2(81.28,50.8) v2(81.28,45.72) v2(81.28,20.32) v2(81.28,15.24) v2(81.28,10.16) v2(81.28,5.08) v2(81.28,1.52) v2(86.36,95) v2(86.36,94.49) v2(86.36,93.98) v2(86.36,91.44) v2(86.36,86.36) v2(86.36,81.28) v2(86.36,76.2) v2(86.36,71.12) v2(86.36,50.8) v2(86.36,45.72) v2(86.36,20.32) v2(86.36,15.24) v2(86.36,10.16) v2(86.36,5.08) v2(86.36,1.52) v2(86.87,94.49) v2(87.12,95) v2(87.12,93.98) v2(90.68,94.49) v2(90.93,95) v2(90.93,93.98) v2(91.44,95) v2(91.44,93.98) v2(91.44,91.44) v2(91.44,86.36) v2(91.44,81.28) v2(91.44,71.12) v2(91.44,50.8) v2(91.44,45.72) v2(91.44,10.16) v2(91.44,5.08) v2(91.44,1.52) v2(96.52,86.36) v2(96.52,81.28) v2(96.52,76.2) v2(96.52,71.12) v2(96.52,66.04) v2(96.52,50.8) v2(96.52,45.72) v2(96.52,20.32) v2(96.52,15.24) v2(100.08,86.36) v2(100.08,81.28) v2(100.08,76.2) v2(100.08,71.12) v2(100.08,66.04) v2(100.08,60.96) v2(100.08,55.88) v2(100.08,50.8) v2(100.08,45.72) v2(100.08,40.64) v2(100.08,35.56) v2(100.08,30.48) v2(100.08,25.4) v2(100.08,20.32) v2(100.08,15.24) v2(100.08,10.16)
PGOOD/TJ: length 53.1
  TOP w0.254: U1.20 50.55,52.71 51.05,53.21 v1(51.05,53.98) ; 42.64,91.44 JP2.2
  TOP w0.508: TP9.1 42.64,91.44
  LAYER_3 w0.254: v1(51.05,53.98) 51.05,54.36 53.72,57.02 53.72,75.44 54.61,76.33 54.61,78.23 v1(54.86,78.49) 54.86,89.92 TP9.1
UNNAMED_1_ADLTC3639_I30_ISET: length 2.3
  TOP w0.254: C7.1 42.25,66.69 U2.11
UNNAMED_1_ADLTC3639_I30_RUN: length 11.2
  TOP w0.254: U2.14 v1(41.52,68.19) ; v1(35.12,73.22) 35.12,73.09 34.76,72.74 C6.1
  LAYER_3 w0.254: v1(41.52,68.19) 41.52,68.21 40.01,69.72 38.61,69.72 v1(35.12,73.22)
UNNAMED_1_ADLTC3639_I30_SS: length 11.7
  TOP w0.254: U2.10 42.22,66.19 C5.1 ; v1(35.18,66.17) 35.2,66.19 U2.7
  LAYER_3 w0.254: v1(42.67,65.15) 42.16,64.64 37.47,64.64 35.94,66.17 v1(35.18,66.17)
UNNAMED_2_7402V2_I1_1Y: length 2.8
  TOP w0.254: U3.5 74.38,79.42 74.63,79.17 74.63,77.47 R10.1
UNNAMED_2_7402V2_I1_2Y: length 4.2
  TOP w0.127: U3.3 v1(73.3,78.13)
  TOP w0.381: R11.1 v1(74.04,80.77)
  LAYER_3 w0.254: v1(73.3,78.13) 73.3,80.03 v1(74.04,80.77)
UNNAMED_2_7402V2_I29_1Y: length 2.9
  TOP w0.254: U4.5 56.72,79.42 57.02,79.12 57.02,78.23 56.85,78.05 R16.1
UNNAMED_2_7402V2_I29_2Y: length 4.5
  TOP w0.127: v1(55.65,77.98) 55.65,78.04 U4.3
  TOP w0.381: R17.1 v1(56.26,80.77)
  LAYER_3 w0.254: v1(55.65,77.98) 55.88,78.21 55.88,80.39 v1(56.26,80.77)
UNNAMED_2_7402V2_I64_1Y: length 2.7
  TOP w0.127: U5.7 64.11,80.11
  TOP w0.254: 64.11,80.11 64.77,80.77 R25.1
UNNAMED_2_ADMAX17617A_I102_GN: length 6.5
  TOP w0.254: 47.88,47.86 U1.4
  TOP w0.508: 47.88,47.86 47.88,44.45 46.45,43.02 Q1.4
UNNAMED_2_ADMAX17617A_I102_IMON: length 47.8
  TOP w0.254: C22.1 50.42,55.07 50.42,53.34 50.1,53.02 50.1,51.62 U1.21
  LAYER_3 w0.254: TP15.1 33.02,87.63 33.02,82.8 42.93,72.9 42.93,70.93 51.24,62.61 51.24,56.32 51.05,56.13 v1(51.05,55.75)
UNNAMED_2_ADMAX17617A_I102_IN1:
  vias: v2(41.91,48.9) v2(41.91,47.62) v2(41.91,46.35) v2(41.91,45.09) v2(43.18,48.9) v2(43.18,47.62) v2(43.18,46.35) v2(43.18,45.09) v2(44.45,48.9) v2(44.45,47.62) v2(44.45,46.35) v2(44.45,45.09) v2(45.72,48.9) v2(45.72,47.62) v2(45.72,46.35) v2(45.72,45.09) v2(49.85,50.04) v2(49.85,49.53) v2(49.85,49.02) v2(50.48,50.04) v2(50.48,49.53) v2(50.48,49.02) v2(51.12,50.04) v2(51.12,49.53) v2(51.12,49.02) v2(51.75,50.04) v2(51.75,49.53) v2(51.75,49.02)
UNNAMED_2_ADMAX17617A_I102_ISTART: length 4.6
  TOP w0.254: R14.1 54.36,54.99 52.05,52.68 U1.17
UNNAMED_2_ADMAX17617A_I102_OUTUV: length 6.5
  TOP w0.254: R20.2 R19.1 55.63,54.99 54.23,53.59 53.73,53.59 52.55,52.41 U1.16
UNNAMED_2_ADMAX17617A_I102_OVFB: length 4
  TOP w0.254: 56.77,48.84 56.57,48.84 54.76,50.65 U1.14
UNNAMED_2_ADMAX17617A_I102_PLIM: length 4.4
  TOP w0.254: U1.15 54.31,52.32 55.24,52.32 56.31,53.39 R23.2
UNNAMED_2_ADMAX17617A_I102_SETI: length 4.4
  TOP w0.254: R1.1 47.24,53.72 48.36,52.6 U1.1
UNNAMED_2_ADMAX17617A_I102_UVLO: length 7.1
  TOP w0.254: U1.2 47.39,50.65 47.12,50.93 47.12,52.96 45.97,54.1 R13.1 R12.2
UNNAMED_2_ADMAX17617A_I102_VCC: length 3.8
  TOP w0.254: U1.23 49,51.62 49,52.86 48.51,53.34 C15.1
UNNAMED_2_CN3P_I68_N1: length 2.7
  TOP w0.254: JP2.1 42.67,93.22 45.03,93.22 R18.2
UNNAMED_2_CN3P_I68_N3: length 2.6
  TOP w0.254: JP2.3 42.61,89.41 R28.1
VOUT: length 21.2
  TOP w0.254: R27.1 v2(58.04,51.12)
  TOP w0.508: R20.1 56.9,57.28 v2(57.15,57.53)
  LAYER_3 w0.254: v2(57.15,57.53) 58.04,56.64 v2(58.04,51.12) 58.04,44.7 55.37,42.04 v2(55.37,39.24)

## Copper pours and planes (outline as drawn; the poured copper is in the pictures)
3V3 on TOP: 46.1,93.6 46.1,92.58 47.75,92.58 47.75,93.6
3V3 on TOP: 52.45,57.78 52.45,57.28 52.58,57.15 52.58,56.01 53.59,56.01 53.59,57.78
3V3 on TOP: 60.58,78.11 60.58,80.14 59.31,80.14 59.31,78.11
3V3 on TOP: 78.74,78.11 78.74,80.14 77.09,80.14 77.09,78.11
3V3 on TOP: 41.53,70.1 44.07,70.1 44.07,73.15 45.72,73.15 45.72,75.69 44.07,75.69 44.07,80.9 37.85,80.9 37.85,73.79 41.53,73.79
3V3 on TOP: 55.12,79.2 55.12,80.04 52.83,80.04 52.83,78.99 54.48,78.99 54.48,79.2
3V3 on TOP: 63.88,79.07 63.88,79.91 60.83,79.88 60.58,80.14 60.45,80.14 60.45,78.87 63.25,78.87 63.25,79.07
3V3 on TOP: 72.9,93.85 72.9,92.84 71.37,92.84 71.37,93.85
3V3 on TOP: 72.77,79.2 72.77,80.04 70.1,80.04 70.1,79.5 69.6,78.99 68.45,78.99 68.45,78.23 70.36,78.23 70.99,78.87 72.14,78.87 72.14,79.2
VIN on TOP: 9.52,13.97 13.34,13.97
VIN on TOP: 26.42,69.72 26.42,67.56 27.81,67.56 27.81,65.53 23.88,65.53 23.88,69.72
VIN on TOP: 44.96,43.81 44.96,37.97 43.69,37.97 28.07,22.35 13.72,22.35 13.34,21.97 13.34,14.1 9.53,14.1 9.53,21.97 9.14,22.35 4.32,22.35 3.81,22.86 3.81,43.18 4.45,43.81
VIN on TOP: 56.26,52.45 56.26,50.67 57.28,50.67 57.28,52.45
VIN on TOP: 45.21,56.13 45.21,57.91 44.2,57.91 44.2,56.13
VIN on LAYER_3: 25.27,67.56 25.27,56.13 31.75,49.66 31.75,44.83 33.53,43.05 33.53,41.78 31.75,41.78 29.84,43.69 29.84,49.02 23.62,55.24 23.62,67.56
FLAG on TOP: 52.58,55.75 52.58,54.61 53.59,54.61 53.59,55.75
GROUND on TOP: 1.27,95.25 100.33,95.25 100.33,1.27 1.27,1.27 ; 4 cut-outs
GROUND on BOTTOM: 1.27,95.25 100.33,95.25 100.33,1.27 1.27,1.27
GROUND on LAYER_2: 1.27,95.25 100.33,95.25 100.33,1.27 1.27,1.27
GROUND on LAYER_3: 1.27,95.25 1.27,1.27 100.33,1.27 100.33,95.25
UNNAMED_1_ADLTC3639_I30_ISET on TOP: 43.18,68.96 43.18,66.55 41.91,66.55 41.91,68.96
UNNAMED_1_ADLTC3639_I30_RUN on TOP: 23.88,70.1 23.88,77.72 30.86,77.72 35.43,73.15 35.43,70.23 35.05,69.85 35.05,68.45 36.96,68.45 36.96,67.82 33.66,67.82 33.66,70.1
UNNAMED_1_ADLTC3639_I30_SS on TOP: 41.91,66.29 41.91,64.9 43.18,64.9 43.18,66.29
UNNAMED_1_ADLTC3639_I30_SW on TOP: 36.96,68.96 36.96,69.47 36.58,69.85 36.58,73.28 37.47,74.17 37.47,80.9 35.81,80.9 34.8,79.88 34.8,74.42 35.81,73.41 35.81,69.85 35.43,69.47 35.43,68.96
UNNAMED_1_CAP_I4_N1 on TOP: 26.8,69.72 26.8,67.94 28.19,67.94 28.19,65.53 33.27,65.53 33.27,69.72
UNNAMED_1_DIOLED_I24_P on TOP: 44.45,77.22 44.45,75.95 46.1,75.95 46.1,74.55 48.13,74.55 48.13,77.22
UNNAMED_2_7402V2_I1_2Y on TOP: 75.18,80.26 75.18,81.28 73.79,81.28 73.79,80.26
UNNAMED_2_7402V2_I29_2Y on TOP: 57.4,81.28 57.4,80.26 56.01,80.26 56.01,81.28
UNNAMED_2_ADMAX17617A_I102_GN on TOP: 47.6,48.13 48.41,48.13 48.41,46.86 47.9,46.35 47.6,46.35
UNNAMED_2_ADMAX17617A_I102_IMON on TOP: 50.16,55.75 50.16,54.74 50.29,54.61 52.32,54.61 52.32,55.82 52.2,55.94 50.86,55.94 50.67,55.75
UNNAMED_2_ADMAX17617A_I102_IN1 on TOP: 43.81,52.32 43.81,49.66 41.02,49.66 41.02,44.07 46.35,44.07 47.12,44.83 47.12,48.26 47.5,48.64 54.36,48.64 54.36,50.04 52.7,50.04 52.26,50.48 49.34,50.48 48.9,50.04 46.99,50.04 46.23,50.8 46.23,52.32
UNNAMED_2_ADMAX17617A_I102_IN1 on BOTTOM: 52.2,50.42 52.2,47.24 49.53,44.58 41.4,44.58 41.4,49.28 48.51,49.28 49.66,50.42
UNNAMED_2_ADMAX17617A_I102_IN1 on LAYER_3: 41.4,49.28 41.4,44.58 49.53,44.58 52.2,47.24 52.2,50.42 49.66,50.42 48.51,49.28
UNNAMED_2_ADMAX17617A_I102_ISTART on TOP: 53.85,55.75 53.85,54.61 54.86,54.61 54.86,55.75
UNNAMED_2_ADMAX17617A_I102_OUTUV on TOP: 55.24,54.61 55.24,55.88 57.78,55.88 57.91,56.01 57.91,57.66 62.61,57.66 62.61,54.61 57.15,54.61 56.9,54.36 55.5,54.36
UNNAMED_2_ADMAX17617A_I102_OVFB on TOP: 59.69,49.66 59.94,49.4 59.94,48.01 60.83,48.01 60.83,44.7 56.13,44.7 55.75,45.09 55.75,49.66
UNNAMED_2_ADMAX17617A_I102_PLIM on TOP: 52.92,52.11 52.92,51 54.01,51 54.01,52.11
UNNAMED_2_ADMAX17617A_I102_PLIM on TOP: 56.52,54.23 55.75,53.47 55.75,52.7 59.69,52.7 59.94,52.96 59.94,54.23
UNNAMED_2_ADMAX17617A_I102_SETI on TOP: 46.74,55.75 46.74,54.61 47.75,54.61 47.75,55.75
UNNAMED_2_ADMAX17617A_I102_UVLO on TOP: 46.48,54.61 46.48,55.88 43.94,55.88 43.69,56.13 43.69,57.53 38.99,57.53 38.99,54.74 43.69,54.74 43.81,54.61
UNNAMED_2_ADMAX17617A_I102_VCC on TOP: 48.01,55.75 48.01,54.61 48.77,54.61 48.9,54.74 48.9,55.75
UNNAMED_2_CN3P_I11_N1 on TOP: 77.22,94.11 77.22,92.58 75.69,92.58 75.44,92.84 73.15,92.84 73.15,93.85 75.44,93.85 75.69,94.11
UNNAMED_2_CN3P_I68_N1 on TOP: 45.85,93.6 45.85,92.58 41.78,92.58 41.78,94.11 43.43,94.11 43.94,93.6
UNNAMED_2_CN3P_I68_N3 on TOP: 45.85,89.92 45.85,88.9 43.31,88.9 43.05,88.65 41.78,88.65 41.78,90.04 43.05,90.04 43.18,89.92
UNNAMED_2_DIOLED4PV5_I19_C1 on TOP: 76.83,79.25 76.83,81.28 75.56,81.28 75.56,79.25
UNNAMED_2_DIOLED4PV5_I19_C2 on TOP: 76.83,76.96 76.83,78.99 75.56,78.99 75.56,76.96
UNNAMED_2_DIOLED4PV5_I31_C1 on TOP: 59.05,79.25 59.05,81.28 57.78,81.28 57.78,79.25
UNNAMED_2_DIOLED4PV5_I31_C2 on TOP: 59.05,76.96 59.05,78.99 57.78,78.99 57.78,76.96
UNNAMED_2_DIOLED4PV5_I74_C2 on TOP: 67.69,78.23 67.69,78.99 66.42,78.99 66.42,79.88 66.8,80.26 67.94,80.26 67.94,81.28 66.29,81.28 66.29,80.26 66.04,80.01 66.04,78.23
UNNAMED_2_DIOTVS_I103_P on TOP: 42.99,30.48 42.99,26.92 53.91,26.92 53.91,30.48
VOUT on TOP: 49.53,48.26 54.48,48.26 55.37,47.37 55.37,44.96 55.88,44.45 97.16,44.45 97.79,43.81 97.79,22.86 97.16,22.23 92.46,22.23 92.08,21.84 92.08,13.97 88.27,13.97 88.27,21.84 87.88,22.23 76.71,22.23 60.96,37.97 49.53,37.97 49.53,33.4 44.07,33.4 44.07,36.7 44.45,37.08 45.59,37.08 45.97,37.47 45.97,40.89 46.1,41.02 47.12,41.02 49.78,43.69 49.78,46.35 49.53,46.61
VOUT on TOP: 57.4,56.13 57.4,57.91 56.39,57.91 56.39,56.13
VOUT on TOP: 88.27,13.97 92.08,13.97
VOUT on TOP: 57.53,52.45 57.53,49.91 58.55,49.91 58.55,52.45

Small or netless copper shapes (teardrops, artwork), in the pictures only: 14 on TOP, 1 on BOTTOM, 13 on LAYER_3

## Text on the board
User.Comments: JP1, JP2: INSTALL SHUNT ACROSS PINS 1 - 2
Ref Des/Silkscreen Top: 4Vin Min | 30V Max Continuous | 75V Max Transient | Current Limit | Output UVLO | Input UVLO | CLMode | OVFB | PLIM | AutoRetry | 24Win | 28V | 2A | 5V | 80V, 2A POWER LIMITER WITH REVERSE | POLARITY AND LOSS OF GND PROTECTION | MAX17617AEVKIT#
DIMENSION: "0"
User.15: PER IPC-4552 LATEST REVISION | ENIG (Electroless Nickel/Immersion Gold) | LAYER 2 | LAYER 3 | 7.    VIA SIZE LESS THAN OR EQUAL TO 0.012" SHALL BE PLUGGED | AND COVERED WITH SOLDER MASK.
User.17: 08-      -07 | L2 GND/SIGNAL
User.18: 08-      -08 | L3 GND/SIGNAL
User.24: IN | OUT | SUPPLY | POWER | 30V | ADJ | LOAD | V | I | A | - | +
User.45: FIGURE | SIZE | 6.0 | 10.0 | 35.0 | 70.0 | 100.0 | 172.0 | 187.0 | PLATED | NON-PLATED | DRILL CHART: TOP to BOTTOM | ALL UNITS ARE IN MILS | QTY | 23 | 393 | 6 | 4 | TOLERANCE/NOTES | NO SECONDARY SIDE COMPONENTS
